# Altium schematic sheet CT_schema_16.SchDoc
size 389 x 385 mm
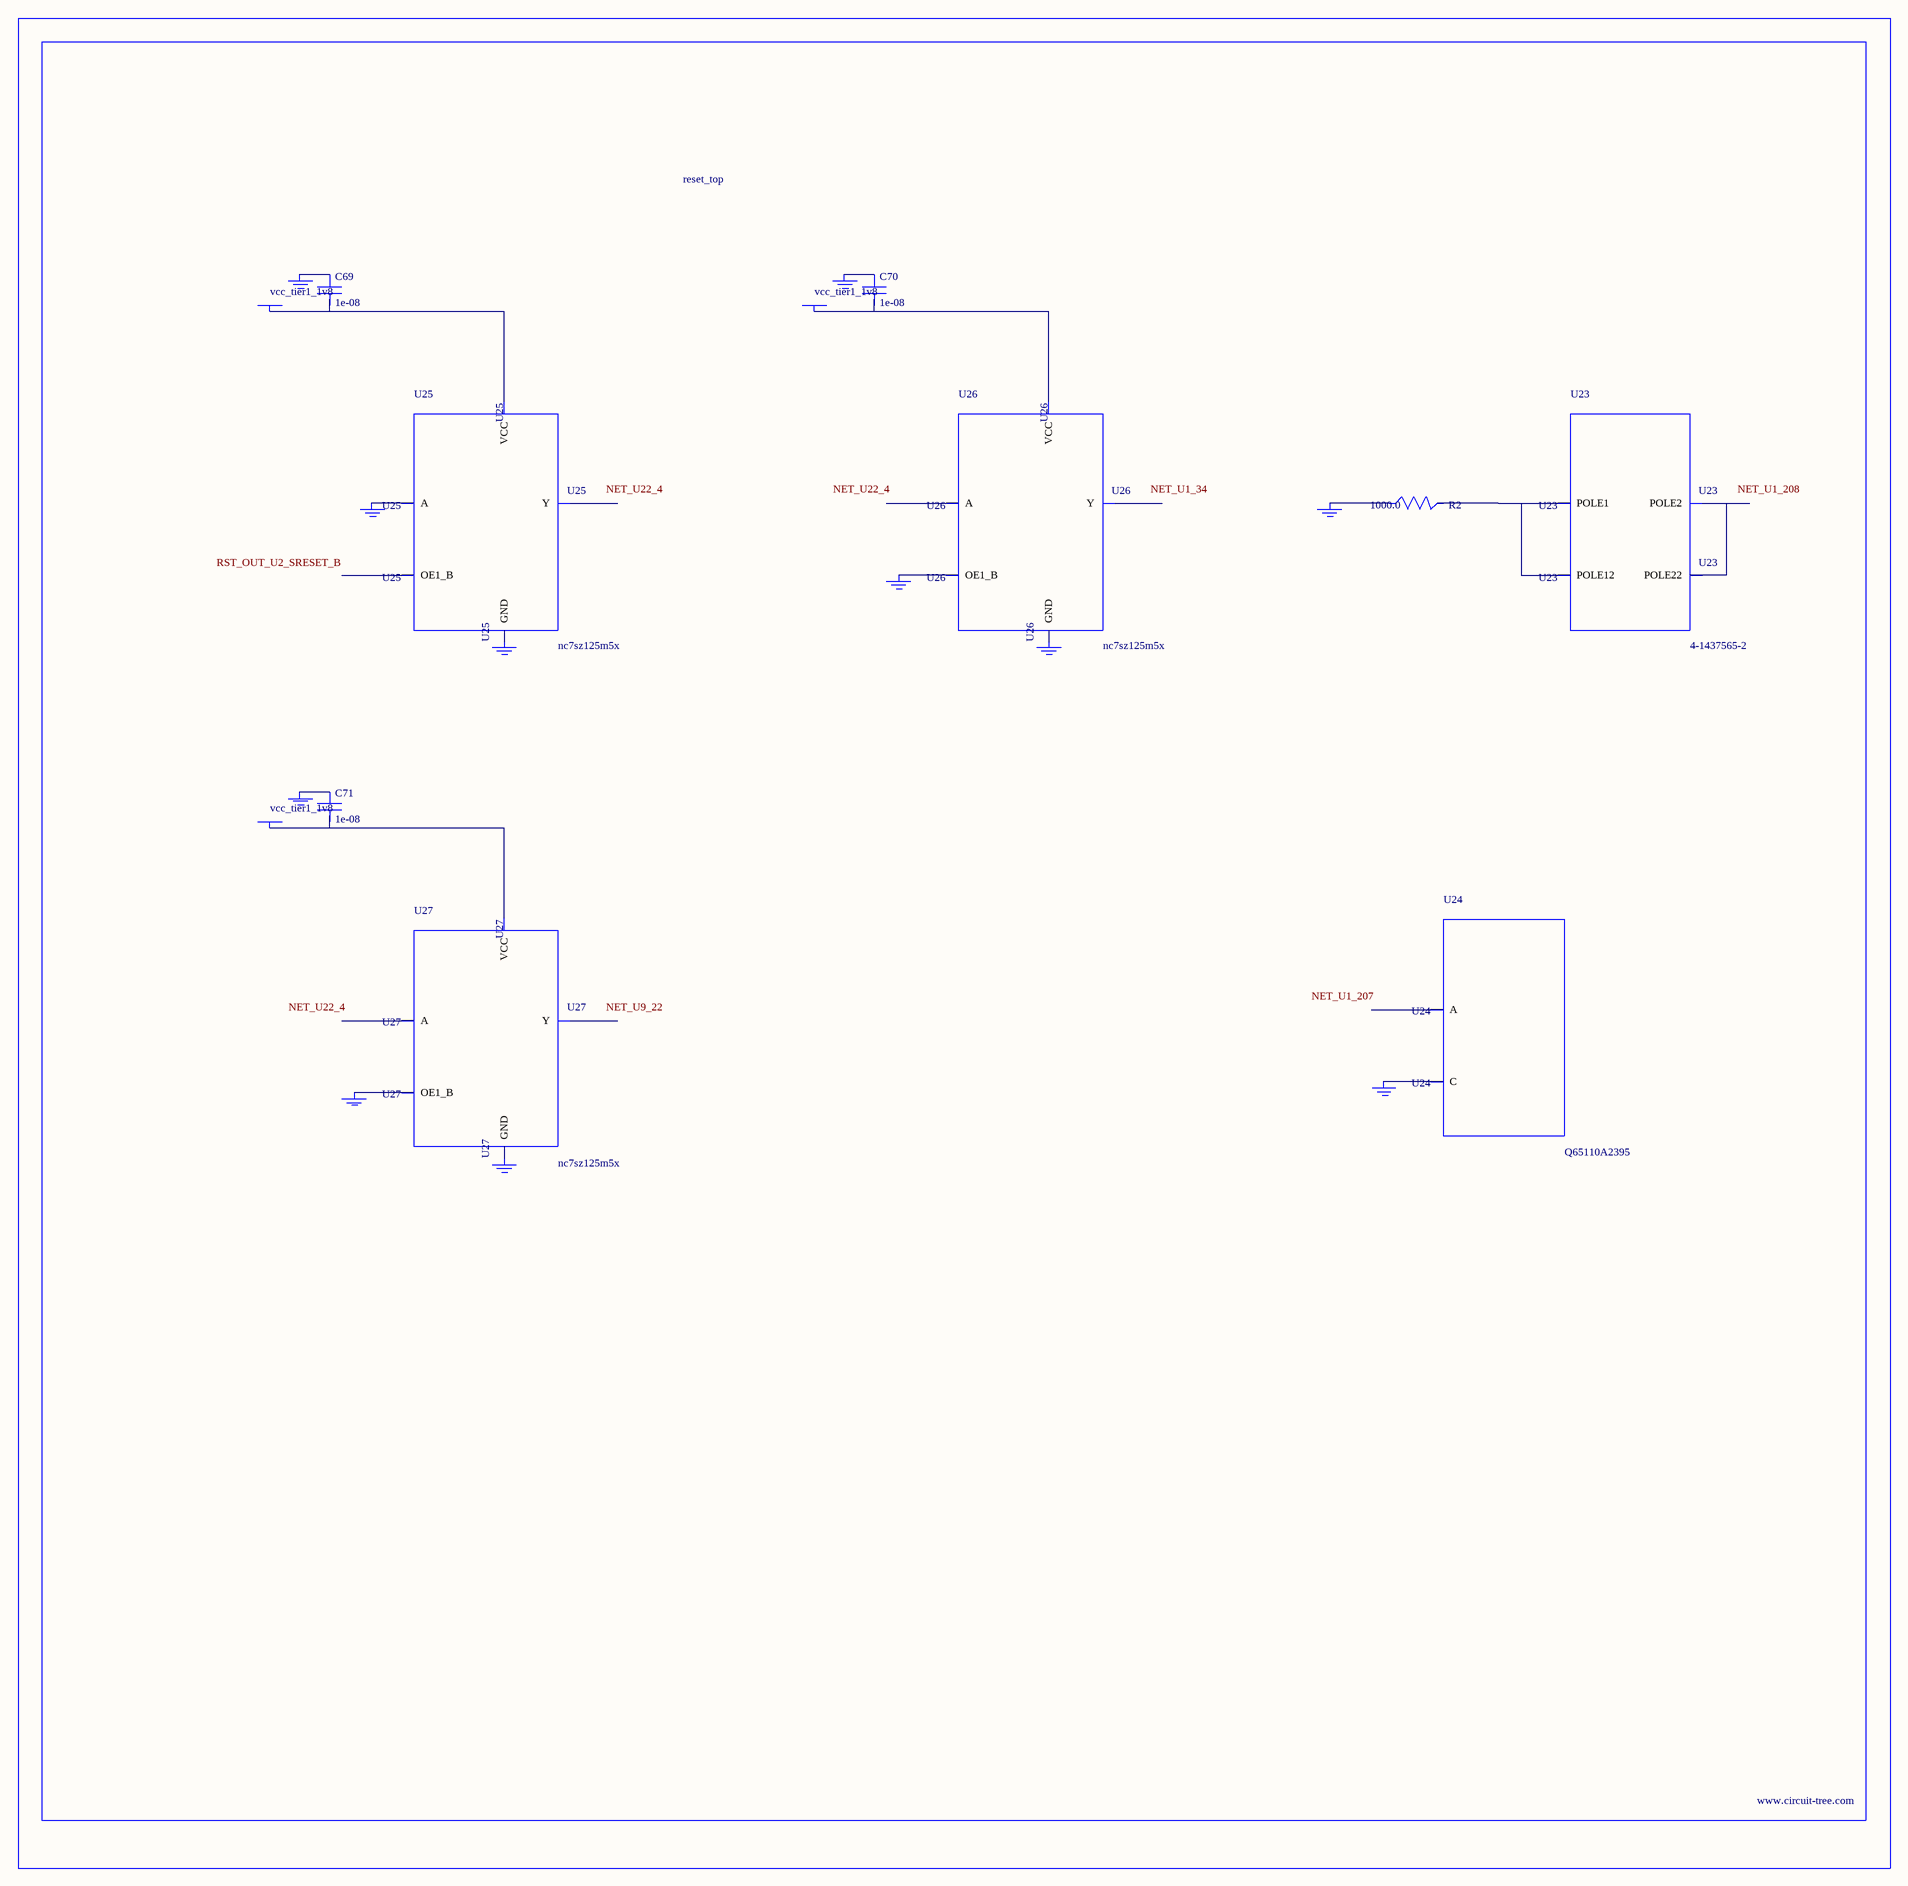
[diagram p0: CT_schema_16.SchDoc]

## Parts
BORDER15  (no value)
C69  1e-08  [C0402]
C70  1e-08  [C0402]
C71  1e-08  [C0402]
GND_INSTANCE_15_0  (no value)
GND_INSTANCE_15_1  (no value)
GND_INSTANCE_15_2  (no value)
GND_INSTANCE_15_3  (no value)
GND_INSTANCE_15_4  (no value)
GND_INSTANCE_15_5  (no value)
GND_INSTANCE_15_6  (no value)
GND_INSTANCE_15_7  (no value)
GND_INSTANCE_15_8  (no value)
GND_INSTANCE_15_9  (no value)
GND_INSTANCE_15_10  (no value)
POWER_INSTANCE_15_0  vcc_tier1_1v8
POWER_INSTANCE_15_1  vcc_tier1_1v8
POWER_INSTANCE_15_2  vcc_tier1_1v8
R2  1000.0  [R0603]
U23  4-1437565-2  [SW_4-1437565-2]
U24  Q65110A2395  [LGM67K-G1J2-24-Z]
U25  nc7sz125m5x  [NC7SZ125M5X]
U26  nc7sz125m5x  [NC7SZ125M5X]
U27  nc7sz125m5x  [NC7SZ125M5X]

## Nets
NetC69_1: C69.1 GND_INSTANCE_15_2.0(GND)
NetC69_2: C69.2 POWER_INSTANCE_15_0.0(PWR) U25.5(VCC)
NetC70_1: C70.1 GND_INSTANCE_15_5.0(GND)
NetC70_2: C70.2 POWER_INSTANCE_15_1.0(PWR) U26.5(VCC)
NetC71_1: C71.1 GND_INSTANCE_15_8.0(GND)
NetC71_2: C71.2 POWER_INSTANCE_15_2.0(PWR) U27.5(VCC)
NetGND_INSTANCE_15_0_0: GND_INSTANCE_15_0.0(GND) R2.1
NetGND_INSTANCE_15_1_0: GND_INSTANCE_15_1.0(GND) U24.C
NetGND_INSTANCE_15_3_0: GND_INSTANCE_15_3.0(GND) U25.2(A)
NetGND_INSTANCE_15_4_0: GND_INSTANCE_15_4.0(GND) U25.3(GND)
NetGND_INSTANCE_15_6_0: GND_INSTANCE_15_6.0(GND) U26.1(OE1_B)
NetGND_INSTANCE_15_7_0: GND_INSTANCE_15_7.0(GND) U26.3(GND)
NetGND_INSTANCE_15_9_0: GND_INSTANCE_15_9.0(GND) U27.1(OE1_B)
NetGND_INSTANCE_15_10_0: GND_INSTANCE_15_10.0(GND) U27.3(GND)
NetR2_2: R2.2 U23.1(POLE1) U23.2(POLE12)
NetU23_3: U23.3(POLE2) U23.4(POLE22)

Not connected (* = marked no-connect by the designer): U24 A; U25 1(OE1_B) 4(Y); U26 2(A) 4(Y); U27 2(A) 4(Y)

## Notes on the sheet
- Labels drawn without touching a wire or pin: NET_U1_34, NET_U1_207, NET_U1_208, NET_U9_22, NET_U22_4, RST_OUT_U2_SRESET_B

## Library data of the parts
BORDER15 = BORDER_PAGE15
C69-C71 = C0402C103K3RAC
GND_INSTANCE_15_0-GND_INSTANCE_15_10 = GND
POWER_INSTANCE_15_0-POWER_INSTANCE_15_2 = PWR
R2 = RC0603JR-071KL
